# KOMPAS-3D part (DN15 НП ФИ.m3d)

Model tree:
1. Операция без истории:1

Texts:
  DN15 НП ФИ
  133 1 134 1 135 1 136 0 50 1|SPDS|133 1 134 1 135 1 136 0 50 1
  125 1 126 1 127 1 128 0 50 1|SPDS|125 1 126 1 127 1 128 0 50 1
  129 1 130 1 131 1 132 0 50 1|SPDS|129 1 130 1 131 1 132 0 50 1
